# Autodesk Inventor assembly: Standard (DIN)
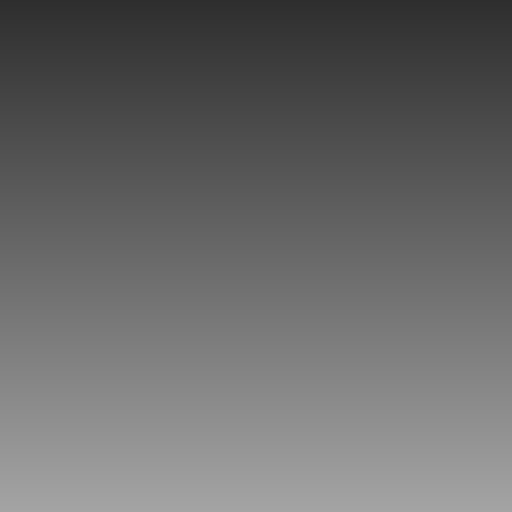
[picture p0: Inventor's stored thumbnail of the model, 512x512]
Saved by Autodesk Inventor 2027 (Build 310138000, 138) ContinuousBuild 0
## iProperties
Created: 2002-07
Part Number: Standard (DIN)
Document SubType Name: Assembly
Control State: 0
Master: False
Checked Out: False
Shininess: 64.0
Length Units: 11269
Angle Units: 11279
Time Units: 11290
Mass Units: 11283
Length Display Precision: 3
Angle Display Precision: 2
Compacted: True
Density: 0.0
Volumn: 0.0
Area: 0.0
PropertySet Name: Model Information
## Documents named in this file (1)
- D:\AUTOBUILD\inventor\Application\App\Templates\en-US\Metric\Standard (DIN).iam
